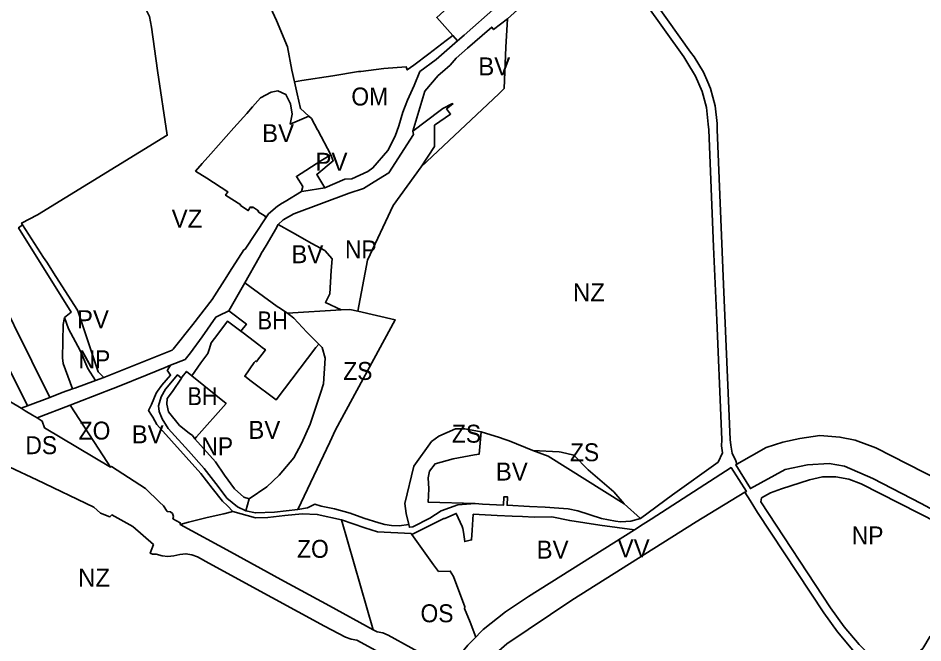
# Model space of a CAD drawing. Extents: x -650451 to -642268, y -1075216 to -1066610.
# Drawn here: x -646153 to -645397, y -1069009 to -1068487 of the extents above; entities that cross this region are included whole.
import ezdxf

# ---------------------------------------------------------------- set-up
doc = ezdxf.new("R2010")
doc.units = 0
doc.header["$LTSCALE"] = 6
doc.layers.add('1', color=7, linetype='Continuous', lineweight=35)
doc.layers.add('2', color=7, linetype='Continuous')
doc.layers.add('3', color=7, linetype='Continuous')

msp = doc.modelspace()

# ---------------------------------------------------------------- linework, layer by layer
at = {"layer": '1'}
for p, q in [((-645785.72, -1068505.75), (-645789.58, -1068501.42)), ((-645963.52, -1068707.92), (-645976.82, -1068731.5)), ((-645882.8, -1068730.56), (-645927.9, -1068733.25)), ((-646088.06, -1068789.6), (-646081.15, -1068787.09)), ((-646145.083, -1068810.83), (-646126.317, -1068803.654)), ((-646150.26, -1068812.81), (-646145.083, -1068810.83)), ((-646109.35, -1068810.23), (-646136.99, -1068820.88)), ((-645959.72, -1068888.55), (-645962.49, -1068898.49)), ((-645646.49, -1068892.56), (-645632.76, -1068904.96)), ((-645856.26, -1068997.79), (-645882.63, -1068905.88))]:
    msp.add_line(p, q, dxfattribs=at)
for points in [[(-646149.04, -1068659.6), (-646149.99, -1068658.12), (-646136.66, -1068651.17), (-646028.19, -1068584.65), (-646036.27, -1068530.56), (-646041.44, -1068494.27), (-646043.13, -1068485.53), (-646048.96, -1068473.76), (-646051.28, -1068467.73), (-646055.39, -1068458.11), (-646056.77, -1068454.35), (-646055.56, -1068450.55), (-646053.26, -1068448.37), (-646043.93, -1068443.44), (-645975.47, -1068407.25), (-645971.94, -1068405.38), (-645964.53, -1068429.83), (-645964.51, -1068429.88), (-645940.28, -1068481.66), (-645936.95, -1068488.76), (-645927.86, -1068510.76), (-645924.25, -1068530.17), (-645922.02, -1068539.96)], [(-645657.63, -1068408.53), (-645654.34, -1068405.65), (-645653.87, -1068424.71), (-645651.53, -1068430.1), (-645591.03, -1068515.22), (-645587.94, -1068519.19), (-645580.2, -1068531.93), (-645576.6, -1068540.35), (-645574.36, -1068545.66), (-645570.55, -1068560.09), (-645568.86, -1068574.89), (-645568.88, -1068579.93), (-645563.42, -1068709.35), (-645557.97, -1068838.77), (-645557.27, -1068843.66), (-645556.12, -1068850.33), (-645553.29, -1068856.55), (-645552.302, -1068859.444)], [(-645673.86, -1068423.84), (-645716.22, -1068462.08), (-645744.06, -1068487.4)], [(-645632.76, -1068904.96), (-645605.99, -1068885.11), (-645567.83, -1068857.79), (-645564.25, -1068849.99), (-645565.26, -1068844.12), (-645564.97, -1068839.07), (-645565.34, -1068825.58), (-645568.99, -1068739.04), (-645571.75, -1068677.77), (-645575.86, -1068580.22), (-645576.29, -1068575.28), (-645577.8, -1068561.45), (-645581.4, -1068548.08), (-645586.82, -1068535.33), (-645594.04, -1068523.44), (-645596.74, -1068519.27), (-645628.94, -1068473.97), (-645655.81, -1068438.19), (-645668.04, -1068424.72), (-645673.86, -1068423.84)], [(-645727.32, -1068453.86), (-645737.89, -1068446.04), (-645746.68, -1068436.15), (-645788.09, -1068473.04), (-645794.06, -1068478.36), (-645803.01, -1068486.33), (-645789.58, -1068501.42)], [(-645727.32, -1068453.86), (-645780.28, -1068501.04), (-645785.72, -1068505.75)], [(-645823.18, -1068581.36), (-645813.08, -1068547.87), (-645801.91, -1068534.79), (-645798.33, -1068531.67), (-645791.92, -1068526.09), (-645786.82, -1068520.27), (-645777.39, -1068511.9), (-645765.18, -1068501.29), (-645757.11, -1068494.29), (-645755.63, -1068496.42), (-645744.06, -1068487.4)], [(-645744.06, -1068487.4), (-645745.39, -1068511.09), (-645746.63, -1068545.61), (-645751.23, -1068549.94), (-645816.02, -1068611.01)], [(-645789.58, -1068501.42), (-645795.14, -1068505.6), (-645809.67, -1068516.54), (-645822.09, -1068526.17), (-645827.73, -1068530.12), (-645828.52, -1068527.64), (-645847.4, -1068528.93), (-645866.58, -1068531.3), (-645868.47, -1068531.53), (-645890.02, -1068534.9), (-645915.92, -1068538.99), (-645922.02, -1068539.96)], [(-645785.72, -1068505.75), (-645803.67, -1068521.32), (-645817.13, -1068531.51), (-645821.8, -1068543.22), (-645827.54, -1068555.34), (-645831.5, -1068565.29), (-645834.88, -1068576.82), (-645837.87, -1068585.42), (-645844.03, -1068597.45), (-645856.41, -1068612.02), (-645860.62, -1068615.07), (-645874.15, -1068621.18), (-645879.74, -1068621.23), (-645896.46, -1068628.59)], [(-646495.416, -1068512.888), (-646487.92, -1068516.87), (-646477.41, -1068526.45), (-646469.51, -1068538.15), (-646461.14, -1068556.34), (-646458.03, -1068569.26), (-646451.82, -1068614.31), (-646446.54, -1068626.14), (-646425.11, -1068652.37), (-646422.32, -1068655.58), (-646413.45, -1068664.71), (-646404.83, -1068671.52), (-646340.36, -1068710.915), (-646337.93, -1068712.4), (-646331.26, -1068716.25), (-646288.59, -1068740.88), (-646229.44, -1068773.53), (-646161.45, -1068807.54), (-646159.1, -1068807.43), (-646150.26, -1068812.81)], [(-646145.083, -1068810.83), (-646204.654, -1068690.937), (-646209.179, -1068681.795), (-646213.659, -1068674.696), (-646221.348, -1068665.144), (-646228.691, -1068658.051), (-646236.707, -1068651.891), (-646243.997, -1068647.407), (-646493.511, -1068509.855)], [(-645909.89, -1068568.71), (-645916.99, -1068562.41), (-645919.73, -1068549.98), (-645922.02, -1068539.96)], [(-645909.89, -1068568.71), (-645925.53, -1068575.33), (-645923.96, -1068566.95), (-645925.25, -1068558.49), (-645929.07, -1068550.59), (-645935.86, -1068547.57), (-645941.5, -1068548.73), (-645950.32, -1068553.38), (-645957.04, -1068560.99), (-645961.86, -1068566.44), (-645972.49, -1068578.4), (-645991.78, -1068600.12), (-645999.05, -1068608.31), (-646004.63, -1068614.59), (-645995.17, -1068620.64), (-645977.65, -1068631.85), (-645979.52, -1068634.8), (-645966.82, -1068642.9), (-645967.14, -1068643.41), (-645960.63, -1068647.57), (-645958.67, -1068644.5), (-645957.36, -1068645.33), (-645956.91, -1068644.61), (-645951.87, -1068647.86), (-645952.28, -1068648.55), (-645946.37, -1068652.24), (-645945.75, -1068653.7)], [(-645823.18, -1068581.36), (-645800.22, -1068563.89), (-645798.03, -1068562.46), (-645789.84, -1068558.19), (-645789.55, -1068558.56), (-645794.88, -1068562.71), (-645791.47, -1068567.01), (-645804.84, -1068576.37), (-645805.04, -1068594.17), (-645816.02, -1068611.01)], [(-645909.89, -1068568.71), (-645907.65, -1068570.7), (-645902.68, -1068580.19), (-645902.51, -1068580.52), (-645902.31, -1068580.46), (-645891.57, -1068600.96)], [(-645935.44, -1068659.31), (-645931.4, -1068655.44), (-645922.43, -1068650.3), (-645876.17, -1068633.1), (-645864.4, -1068629.15), (-645855.41, -1068623.7), (-645843.03, -1068616.2), (-645822.53, -1068584.02), (-645823.18, -1068581.36)], [(-645916.18, -1068631.57), (-645914.86, -1068627.46), (-645920.28, -1068619.1), (-645899.88, -1068606.17), (-645891.57, -1068600.96)], [(-645891.57, -1068600.96), (-645889.69, -1068606.15), (-645903.39, -1068617.33), (-645896.46, -1068628.59)], [(-645816.02, -1068611.01), (-645839.55, -1068643.47), (-645860.91, -1068689.17), (-645868.98, -1068731.71)], [(-645916.18, -1068631.57), (-645914.12, -1068631.26), (-645896.46, -1068628.59)], [(-645916.18, -1068631.57), (-645929.72, -1068639.9), (-645932.11, -1068641.45), (-645936.08, -1068644.03), (-645943.63, -1068650.37), (-645945.75, -1068653.7)], [(-646149.04, -1068659.6), (-646152.41, -1068662.01), (-646108.6, -1068732.56), (-646114.15, -1068737.05)], [(-646081.15, -1068787.09), (-646085.96, -1068782.2), (-646102.39, -1068733.06), (-646103.1, -1068730.94), (-646121.23, -1068702.79), (-646128.98, -1068690.74), (-646131.56, -1068686.74), (-646149.04, -1068659.6)], [(-645945.75, -1068653.7), (-645963.17, -1068679.86), (-645964.19, -1068680.5), (-645976.09, -1068699.08), (-645978.4, -1068702.69), (-645990.79, -1068722.02), (-646006.77, -1068742.76), (-646023.16, -1068763.37), (-646024.22, -1068764.13), (-646081.15, -1068787.09)], [(-645935.44, -1068659.31), (-645937.75, -1068663.29), (-645944.75, -1068675.36), (-645948.72, -1068681.93), (-645948.88, -1068682.2), (-645951.39, -1068686.68), (-645963.52, -1068707.92)], [(-645882.8, -1068730.56), (-645896.03, -1068724.4), (-645892.5, -1068717.07), (-645891.28, -1068697.71), (-645890.35, -1068687.89), (-645896.65, -1068680.96), (-645907.4, -1068675.02), (-645923.6, -1068665.83), (-645935.44, -1068659.31)], [(-646126.317, -1068803.654), (-646186.371, -1068682.825)], [(-645963.52, -1068707.92), (-645936.46, -1068727.71), (-645934.95, -1068728.69), (-645927.9, -1068733.25)], [(-645976.82, -1068731.5), (-645977.94, -1068732.03), (-645984.36, -1068735.06), (-645987.67, -1068736.62), (-645998.94, -1068752.99), (-646008.69, -1068766.47), (-646013.33, -1068772.01), (-646025.54, -1068776.87)], [(-645966.626, -1068748.419), (-645962.078, -1068742.532), (-645976.82, -1068731.5)], [(-645927.9, -1068733.25), (-645925.14, -1068735.32), (-645922.38, -1068737.4), (-645911.64, -1068749.19), (-645901.71, -1068759.09)], [(-645868.98, -1068731.71), (-645837.77, -1068738.91), (-645887.72, -1068830.87), (-645892.53, -1068841.03), (-645919.15, -1068897.29)], [(-645868.98, -1068731.71), (-645875.81, -1068730.14), (-645882.8, -1068730.56)], [(-646107.5, -1068796.63), (-646115.26, -1068775.39), (-646115.86, -1068770.5), (-646115.07, -1068742.74), (-646114.15, -1068737.05)], [(-646088.06, -1068789.6), (-646094.58, -1068779.42), (-646100.92, -1068764.62), (-646110.72, -1068746.41), (-646114.15, -1068737.05)], [(-646007.68, -1068785.56), (-646000.11, -1068774.8), (-645994.29, -1068767.03), (-645993, -1068762.84), (-645991.63, -1068758.23), (-645986.09, -1068750.74), (-645977.81, -1068739.99), (-645966.626, -1068748.419)], [(-645966.626, -1068748.419), (-645964.74, -1068749.84), (-645960.12, -1068753.29), (-645951.68, -1068759.88), (-645948.95, -1068761.91), (-645946.23, -1068763.94), (-645953.54, -1068773.71), (-645954.49, -1068773.32), (-645955.53, -1068774.59), (-645963.46, -1068785.97), (-645958.03, -1068790.12), (-645937.37, -1068805.77), (-645903.97, -1068762.04), (-645901.71, -1068759.09)], [(-645959.72, -1068888.55), (-645944.92, -1068878.3), (-645934.85, -1068868.73), (-645922.49, -1068854.14), (-645916.01, -1068842.31), (-645908.88, -1068825.98), (-645900.29, -1068800.2), (-645897.69, -1068792.48), (-645896.2, -1068770.99), (-645898.72, -1068762.08), (-645901.71, -1068759.09)], [(-646109.35, -1068810.23), (-646080.59, -1068799.05), (-646079.26, -1068798.53), (-646069.79, -1068794.86), (-646045.07, -1068784.78), (-646029.93, -1068778.62), (-646025.54, -1068776.87)], [(-646025.54, -1068776.87), (-646027.84, -1068780.35), (-646028.28, -1068781.01), (-646025.4, -1068785.19), (-646032.81, -1068793.41), (-646036.29, -1068798.5), (-646037.36, -1068800.29), (-646041.46, -1068809.51), (-646043.81, -1068814.66), (-646041.36, -1068818.65), (-646040.4, -1068820.21), (-646036.91, -1068826.37), (-646000.19, -1068867.19), (-645990.8, -1068879.47), (-645981.95, -1068890.37), (-645977.79, -1068894.28), (-645973.36, -1068898.93)], [(-645962.49, -1068898.49), (-645969.47, -1068895.19), (-645978.42, -1068887.77), (-645985.69, -1068878.18), (-645997.28, -1068863.15), (-646010.58, -1068848.21), (-646027.39, -1068829.61), (-646032.45, -1068821.62), (-646034.88, -1068815.39), (-646035.46, -1068810.71), (-646033.43, -1068803.22), (-646029.83, -1068796.91), (-646019.7, -1068784.86), (-646016.36, -1068787.54)], [(-646016.36, -1068787.54), (-646023.94, -1068798.68), (-646028.24, -1068804.53), (-646028.59, -1068809.26), (-646027.13, -1068815.63), (-646017.95, -1068827.09), (-646009.97, -1068833.45), (-646007.27, -1068835.51), (-646005.18, -1068838.43)], [(-646016.36, -1068787.54), (-646015.75, -1068786.64), (-646012.15, -1068781.94), (-646007.68, -1068785.56)], [(-646007.68, -1068785.56), (-645979.15, -1068808.68), (-646003.68, -1068836.72), (-646005.18, -1068838.43)], [(-646126.317, -1068803.654), (-646115.95, -1068799.69), (-646107.5, -1068796.63)], [(-646107.5, -1068796.63), (-646105.32, -1068795.84), (-646088.06, -1068789.6)], [(-646075.56, -1068861.95), (-646081.72, -1068852.51), (-646109.35, -1068810.23)], [(-646136.99, -1068820.88), (-646140.73, -1068818.61), (-646146.85, -1068814.88), (-646150.26, -1068812.81)], [(-646075.56, -1068861.95), (-646130.68, -1068829.21), (-646132.62, -1068823.54), (-646136.99, -1068820.88)], [(-645826.441, -1068909.81), (-645828.71, -1068900.71), (-645829.76, -1068892.24), (-645822.26, -1068861.1), (-645807.42, -1068840.55), (-645801.24, -1068836.04), (-645787.33, -1068829.85), (-645779.72, -1068830.06), (-645766.07, -1068832.57)], [(-645770.96, -1068892.45), (-645810.2, -1068891.3), (-645809.76, -1068880.04), (-645810.22, -1068870.88), (-645808.99, -1068865.25), (-645804.51, -1068859.28), (-645789.33, -1068854.99), (-645771.43, -1068851.77), (-645767.58, -1068851.08), (-645766.07, -1068832.57)], [(-645766.07, -1068832.57), (-645750.71, -1068837.16), (-645746.62, -1068838.62), (-645742.6, -1068840.05), (-645722.69, -1068847.93)], [(-646005.18, -1068838.43), (-645987.85, -1068857.57), (-645980.41, -1068868.55), (-645972.16, -1068880.1), (-645964.34, -1068887.16), (-645959.72, -1068888.55)], [(-645552.302, -1068859.444), (-645527.84, -1068845.59), (-645513.84, -1068841.17), (-645499.8, -1068838.07), (-645482.88, -1068835.58), (-645466.2, -1068836.84), (-645453.59, -1068839.38), (-645436.18, -1068845.91), (-645369.07, -1068879.97)], [(-645722.69, -1068847.93), (-645710.02, -1068852.79), (-645646.49, -1068892.56)], [(-645722.69, -1068847.93), (-645700.79, -1068849.16), (-645699.05, -1068849.57), (-645688.54, -1068852.06), (-645676.5, -1068864.08), (-645655, -1068882.59), (-645646.49, -1068892.56)], [(-646182.57, -1068851.3), (-646137.23, -1068872.6), (-646089.63, -1068895.5), (-646084.1, -1068900.51), (-646076.09, -1068903.48), (-646074.51, -1068901.9), (-646057.13, -1068911.62), (-646039.84, -1068926.67), (-646042.5, -1068933.91), (-646040.65, -1068934.59), (-646037.5, -1068934.7), (-646032.61, -1068936.1), (-646027.69, -1068936.6), (-646022.77, -1068936.12), (-646017.6, -1068934.89), (-646012.64, -1068934.34), (-646007.7, -1068935.18), (-646002.95, -1068936.95), (-645993.5, -1068942.1), (-645940.77, -1068970.74), (-645896.91, -1068994.75), (-645879.17, -1069004.02), (-645874.49, -1069005.73), (-645869.83, -1069006.45), (-645850.79, -1069016.84)], [(-646017.55, -1068909.75), (-646017.39, -1068908.42), (-646023.56, -1068905.05), (-646023.13, -1068903.12), (-646023.92, -1068900.73), (-646025.57, -1068899.39), (-646028.18, -1068898.89), (-646031.31, -1068894.32), (-646034.65, -1068891.12), (-646046.48, -1068879.92), (-646074.78, -1068861.51), (-646075.56, -1068861.95)], [(-645545.679, -1068882.991), (-645544.33, -1068882.17), (-645557.17, -1068862.39), (-645623.92, -1068905.45), (-645630.48, -1068909.6), (-645637.82, -1068914.25)], [(-645377.1, -1068903.78), (-645398.36, -1068892.25), (-645438.7, -1068871.38), (-645462.39, -1068861.11), (-645475.18, -1068859.03), (-645493.25, -1068860.03), (-645512.04, -1068863.96), (-645540.97, -1068879.83), (-645553.23, -1068859.97), (-645552.302, -1068859.444)], [(-645390.75, -1069003.09), (-645397.01, -1069013.46), (-645423.753, -1069034.862), (-645436.6, -1069023.76), (-645450.17, -1069010.02), (-645462.64, -1068995.27), (-645473.98, -1068979.47), (-645532.39, -1068890.9), (-645531.66, -1068887.61), (-645524.13, -1068883.52), (-645515.12, -1068880), (-645491.61, -1068872.47), (-645480.68, -1068870.12), (-645469.68, -1068869.93), (-645458.84, -1068871.88), (-645448.43, -1068875.95), (-645384.33, -1068908.58)], [(-645545.679, -1068882.991), (-645586.28, -1068907.71), (-645690.34, -1068973.16), (-645744.65, -1069009.71), (-645760.07, -1069023.11), (-645773.38, -1069043.46)], [(-645632.76, -1068904.96), (-645641.04, -1068907.11), (-645645.05, -1068907.48), (-645649.58, -1068907.52), (-645653.65, -1068907.01), (-645665.48, -1068904.97), (-645685.13, -1068898.52), (-645693.28, -1068896.78), (-645700.94, -1068896.22), (-645712.38, -1068895.46), (-645725.59, -1068894.76), (-645744.35, -1068893.77), (-645743.88, -1068886.85), (-645744.92, -1068886.77), (-645746.88, -1068886.63), (-645747.25, -1068893.66), (-645764.75, -1068892.77), (-645770.96, -1068892.45)], [(-645419.17, -1069048.02), (-645426.46, -1069041.78), (-645441.38, -1069028.88), (-645455.35, -1069014.76), (-645468.16, -1068999.57), (-645479.67, -1068983.55), (-645534.94, -1068899.86), (-645541.34, -1068889.93), (-645545.679, -1068882.991)], [(-645919.15, -1068897.29), (-645911.18, -1068896.02), (-645904.96, -1068892.79), (-645899.63, -1068894.52), (-645888.54, -1068896.89), (-645875.32, -1068900.46), (-645864.07, -1068904.55), (-645851.56, -1068908.52), (-645846.45, -1068909.84), (-645840.85, -1068910.62), (-645834.4, -1068911.02), (-645826.441, -1068909.81)], [(-645770.96, -1068892.45), (-645785.32, -1068893.32), (-645799.37, -1068898.41), (-645808.87, -1068904.55), (-645823.18, -1068911.82), (-645825.84, -1068912.22), (-645826.441, -1068909.81)], [(-646017.55, -1068909.75), (-646010.48, -1068907.86), (-646004.88, -1068906.5), (-645994.9, -1068904.1), (-645980.93, -1068900.85), (-645973.36, -1068898.93)], [(-645973.36, -1068898.93), (-645954.59, -1068904.41), (-645944.23, -1068904.13), (-645930.1, -1068902.47), (-645915.61, -1068901.02), (-645902.91, -1068901.43), (-645882.63, -1068905.88)], [(-645919.15, -1068897.29), (-645938.5, -1068899.61), (-645954.63, -1068900.16), (-645962.49, -1068898.49)], [(-645823.83, -1068918.35), (-645802.63, -1068907.7), (-645797.01, -1068904.9), (-645796.44, -1068904.9), (-645786.8, -1068900.58), (-645781.88, -1068911.67), (-645781.29, -1068913.2), (-645780.63, -1068916.24), (-645779.68, -1068924.1), (-645776.18, -1068923.26), (-645773.94, -1068922.73), (-645773.4, -1068914.52), (-645772.54, -1068901.36), (-645752.46, -1068902.37), (-645740.11, -1068902.84), (-645731.3, -1068903.25), (-645721.69, -1068903.71), (-645707.03, -1068903.54), (-645691.88, -1068906.55), (-645666.67, -1068910.42), (-645637.82, -1068914.25)], [(-645856.26, -1068997.79), (-645892.77, -1068977.86), (-645933.28, -1068955.74), (-645975.31, -1068932.8), (-646017.55, -1068909.75)], [(-645882.63, -1068905.88), (-645863.03, -1068912.62), (-645852.64, -1068916), (-645824.55, -1068917.37), (-645823.83, -1068918.35)], [(-645637.82, -1068914.25), (-645699.5, -1068953.13), (-645726.46, -1068970.04), (-645745.65, -1068982.8), (-645764.17, -1068997.62), (-645767.3, -1069000.78), (-645769.7, -1069003.19), (-645770.47, -1069003.97)], [(-645770.47, -1069003.97), (-645775.02, -1068991.59), (-645779.83, -1068979.98), (-645779.72, -1068978.8), (-645789.07, -1068953.45), (-645791.76, -1068948.85), (-645801.57, -1068949.19), (-645805.71, -1068943.45), (-645823.83, -1068918.35)], [(-645790.53, -1069027.19), (-645805.16, -1069023.52), (-645843.56, -1069002.41), (-645848.18, -1069000.48), (-645852.91, -1068999.62), (-645856.26, -1068997.79)], [(-645770.47, -1069003.97), (-645777.16, -1069010.72), (-645790.53, -1069027.19)]]:
    msp.add_lwpolyline(points, dxfattribs=at)

# ---------------------------------------------------------------- texts
at = {"layer": '2'}
for s, p in [('BV', (-645768.37, -1068534.647)), ('BV', (-645949.016, -1068590.417)), ('PV', (-645904.403, -1068614.36)), ('VZ', (-646024.545, -1068661.815)), ('BV', (-645924.559, -1068691.577)), ('NZ', (-645689.322, -1068723.484)), ('PV', (-646103.699, -1068745.851)), ('BV', (-646057.959, -1068842.023)), ('BV', (-645960.503, -1068838.316)), ('BV', (-645753.733, -1068873.148)), ('BV', (-645719.642, -1068938.366)), ('VV', (-645651.929, -1068937.334)), ('NZ', (-646102.728, -1068961.775))]:
    msp.add_text(s, height=15, dxfattribs=at).set_placement(p)
for s, width, p in [('OM', 0.95, (-645874.42, -1068559.82)), ('NP', 0.95, (-645879.732, -1068687.578)), ('BH', 0.9, (-645952.7, -1068746.88)), ('NP', 0.95, (-646102.32, -1068779.383)), ('ZS', 0.95, (-645881.15, -1068789.1)), ('BH', 0.9, (-646011.269, -1068810.157)), ('ZS', 0.95, (-645790.379, -1068841.508)), ('NP', 0.95, (-645999.708, -1068852.071)), ('ZS', 0.95, (-645691.737, -1068857.025)), ('OS', 0.95, (-645816.62, -1068991.56))]:
    msp.add_text(s, height=15, dxfattribs=dict(at, width=width)).set_placement(p)
at = {"layer": '3', "width": 0.95}
for s, p in [('ZO', (-646102.227, -1068838.916)), ('DS', (-646146.747, -1068851.116)), ('NP', (-645456.295, -1068926.526)), ('ZO', (-645919.744, -1068937.703))]:
    msp.add_text(s, height=15, dxfattribs=at).set_placement(p)

doc.saveas('drawing.dxf')
